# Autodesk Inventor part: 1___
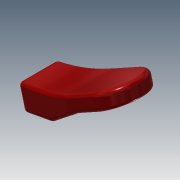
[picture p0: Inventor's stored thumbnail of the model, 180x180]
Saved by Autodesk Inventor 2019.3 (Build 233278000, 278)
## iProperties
Created: 2010-06
Part Number: 1___
Material: Ogólny
Document SubType Name: Modeling
Designer: CADENGINEERING4
Density: 1 g/cm^3
Appearance: Czerwona
Author: CADENGINEERING4
Revision Number: ANY
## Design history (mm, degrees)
feature "NONE"
node "Bryła1"
